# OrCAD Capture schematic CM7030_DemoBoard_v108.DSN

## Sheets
1 00.NOTE: title: CMA175; rev: 1.08; company: C-MEDIA ELECTRONICS Inc.; note: Note; note: 6F., 100, Sec. 4, Civil Boulevard, Taipei, Taiwan, R.O.C.
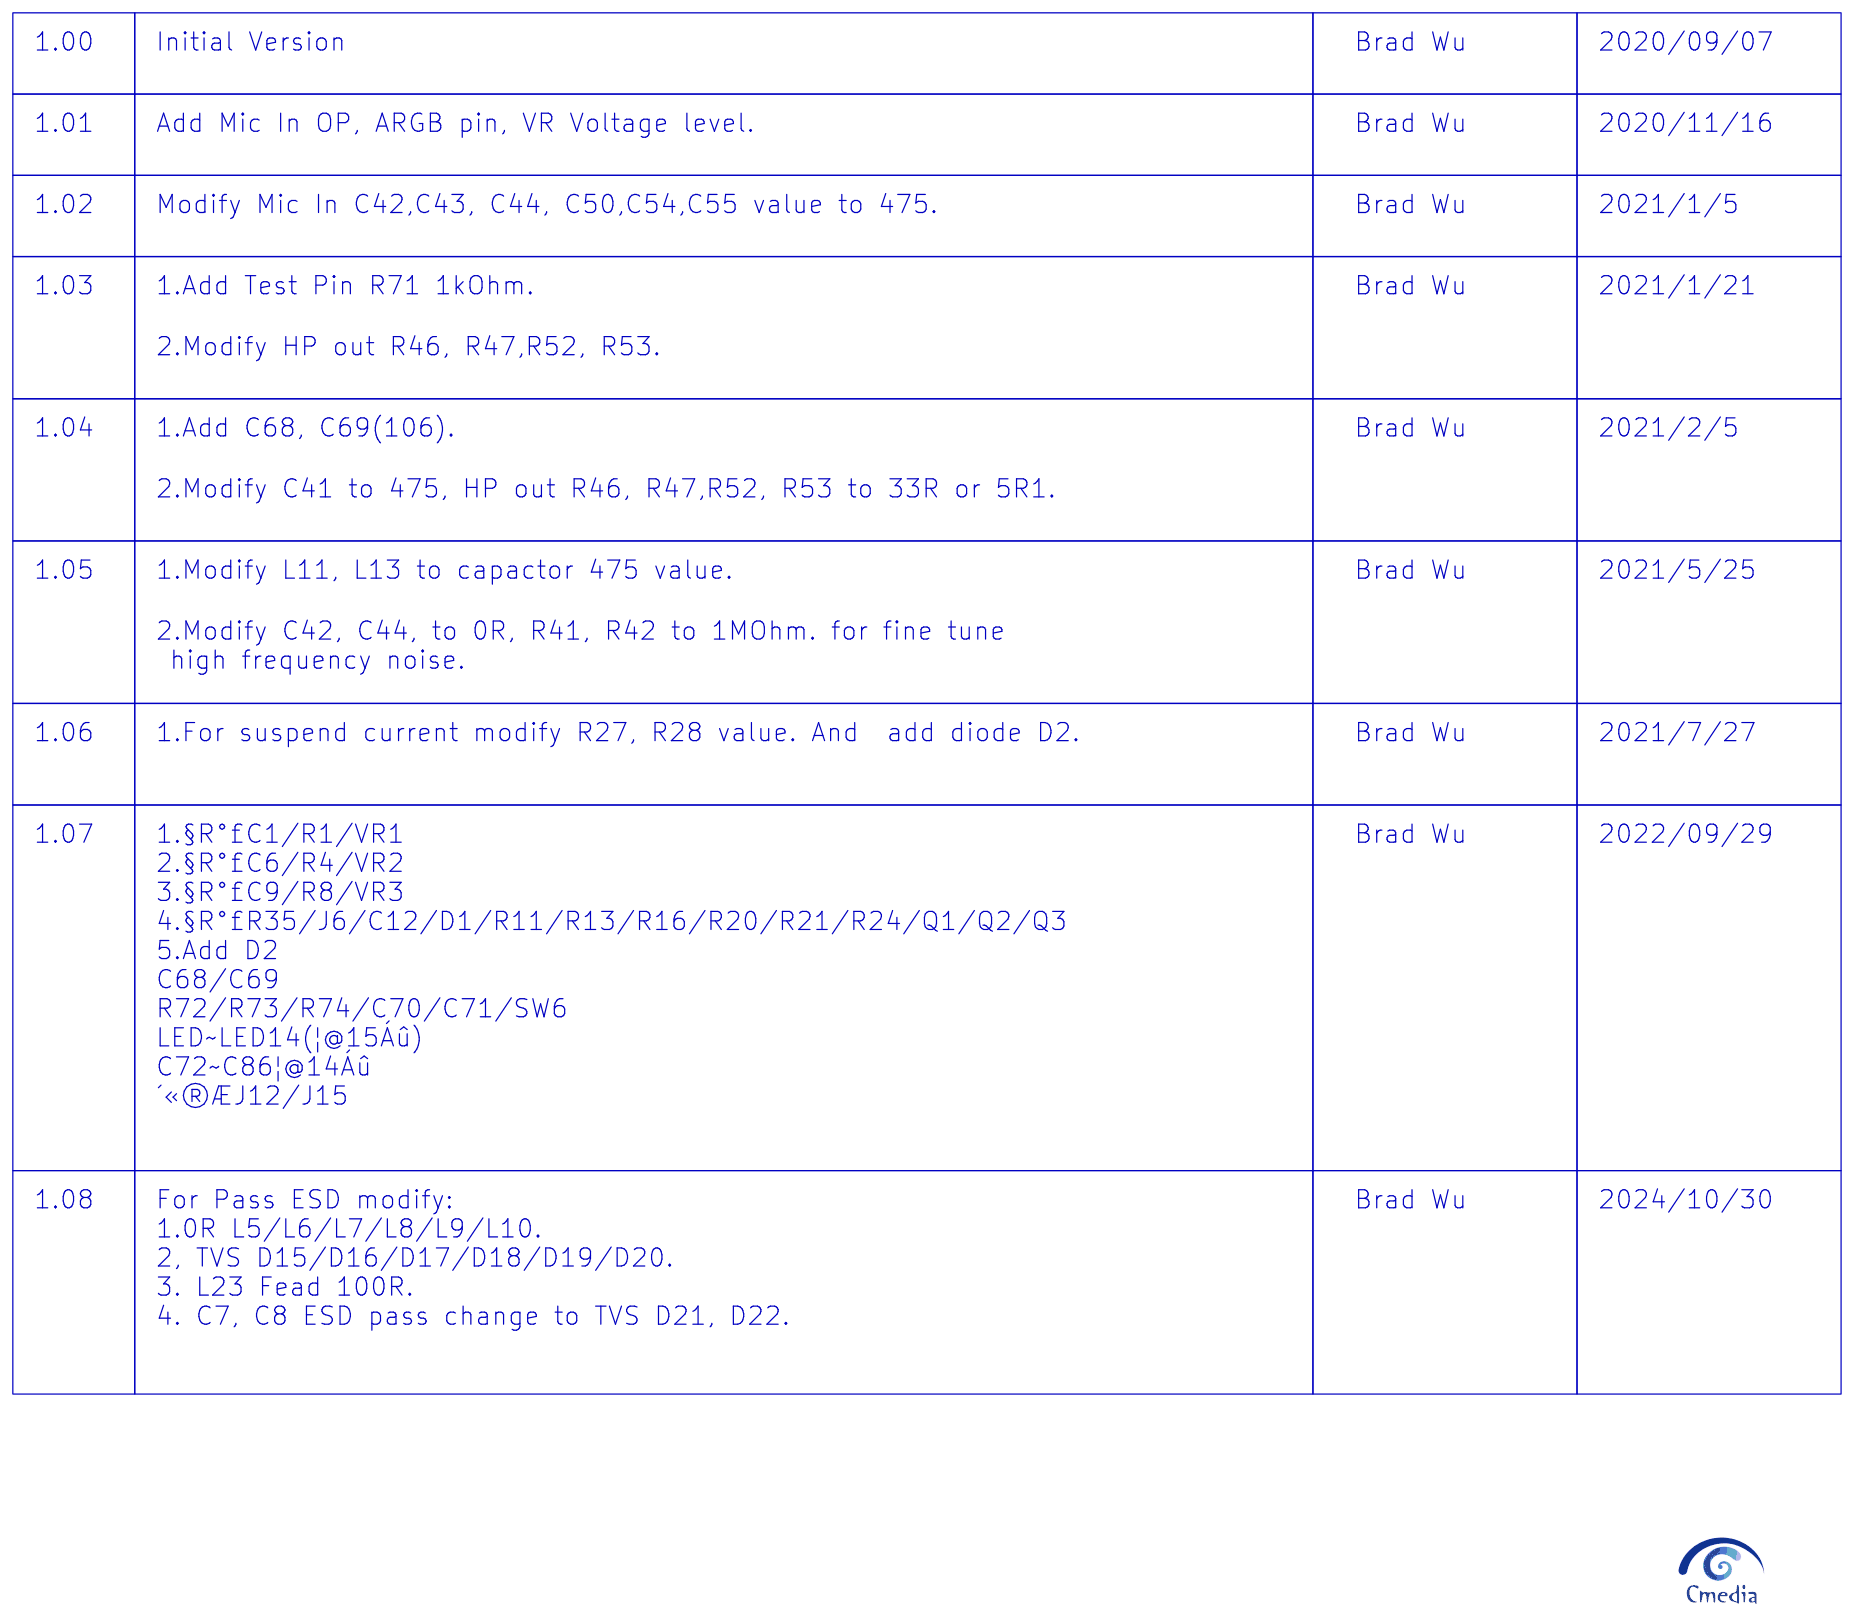
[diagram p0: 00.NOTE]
2 01.BLOCK: note: Block
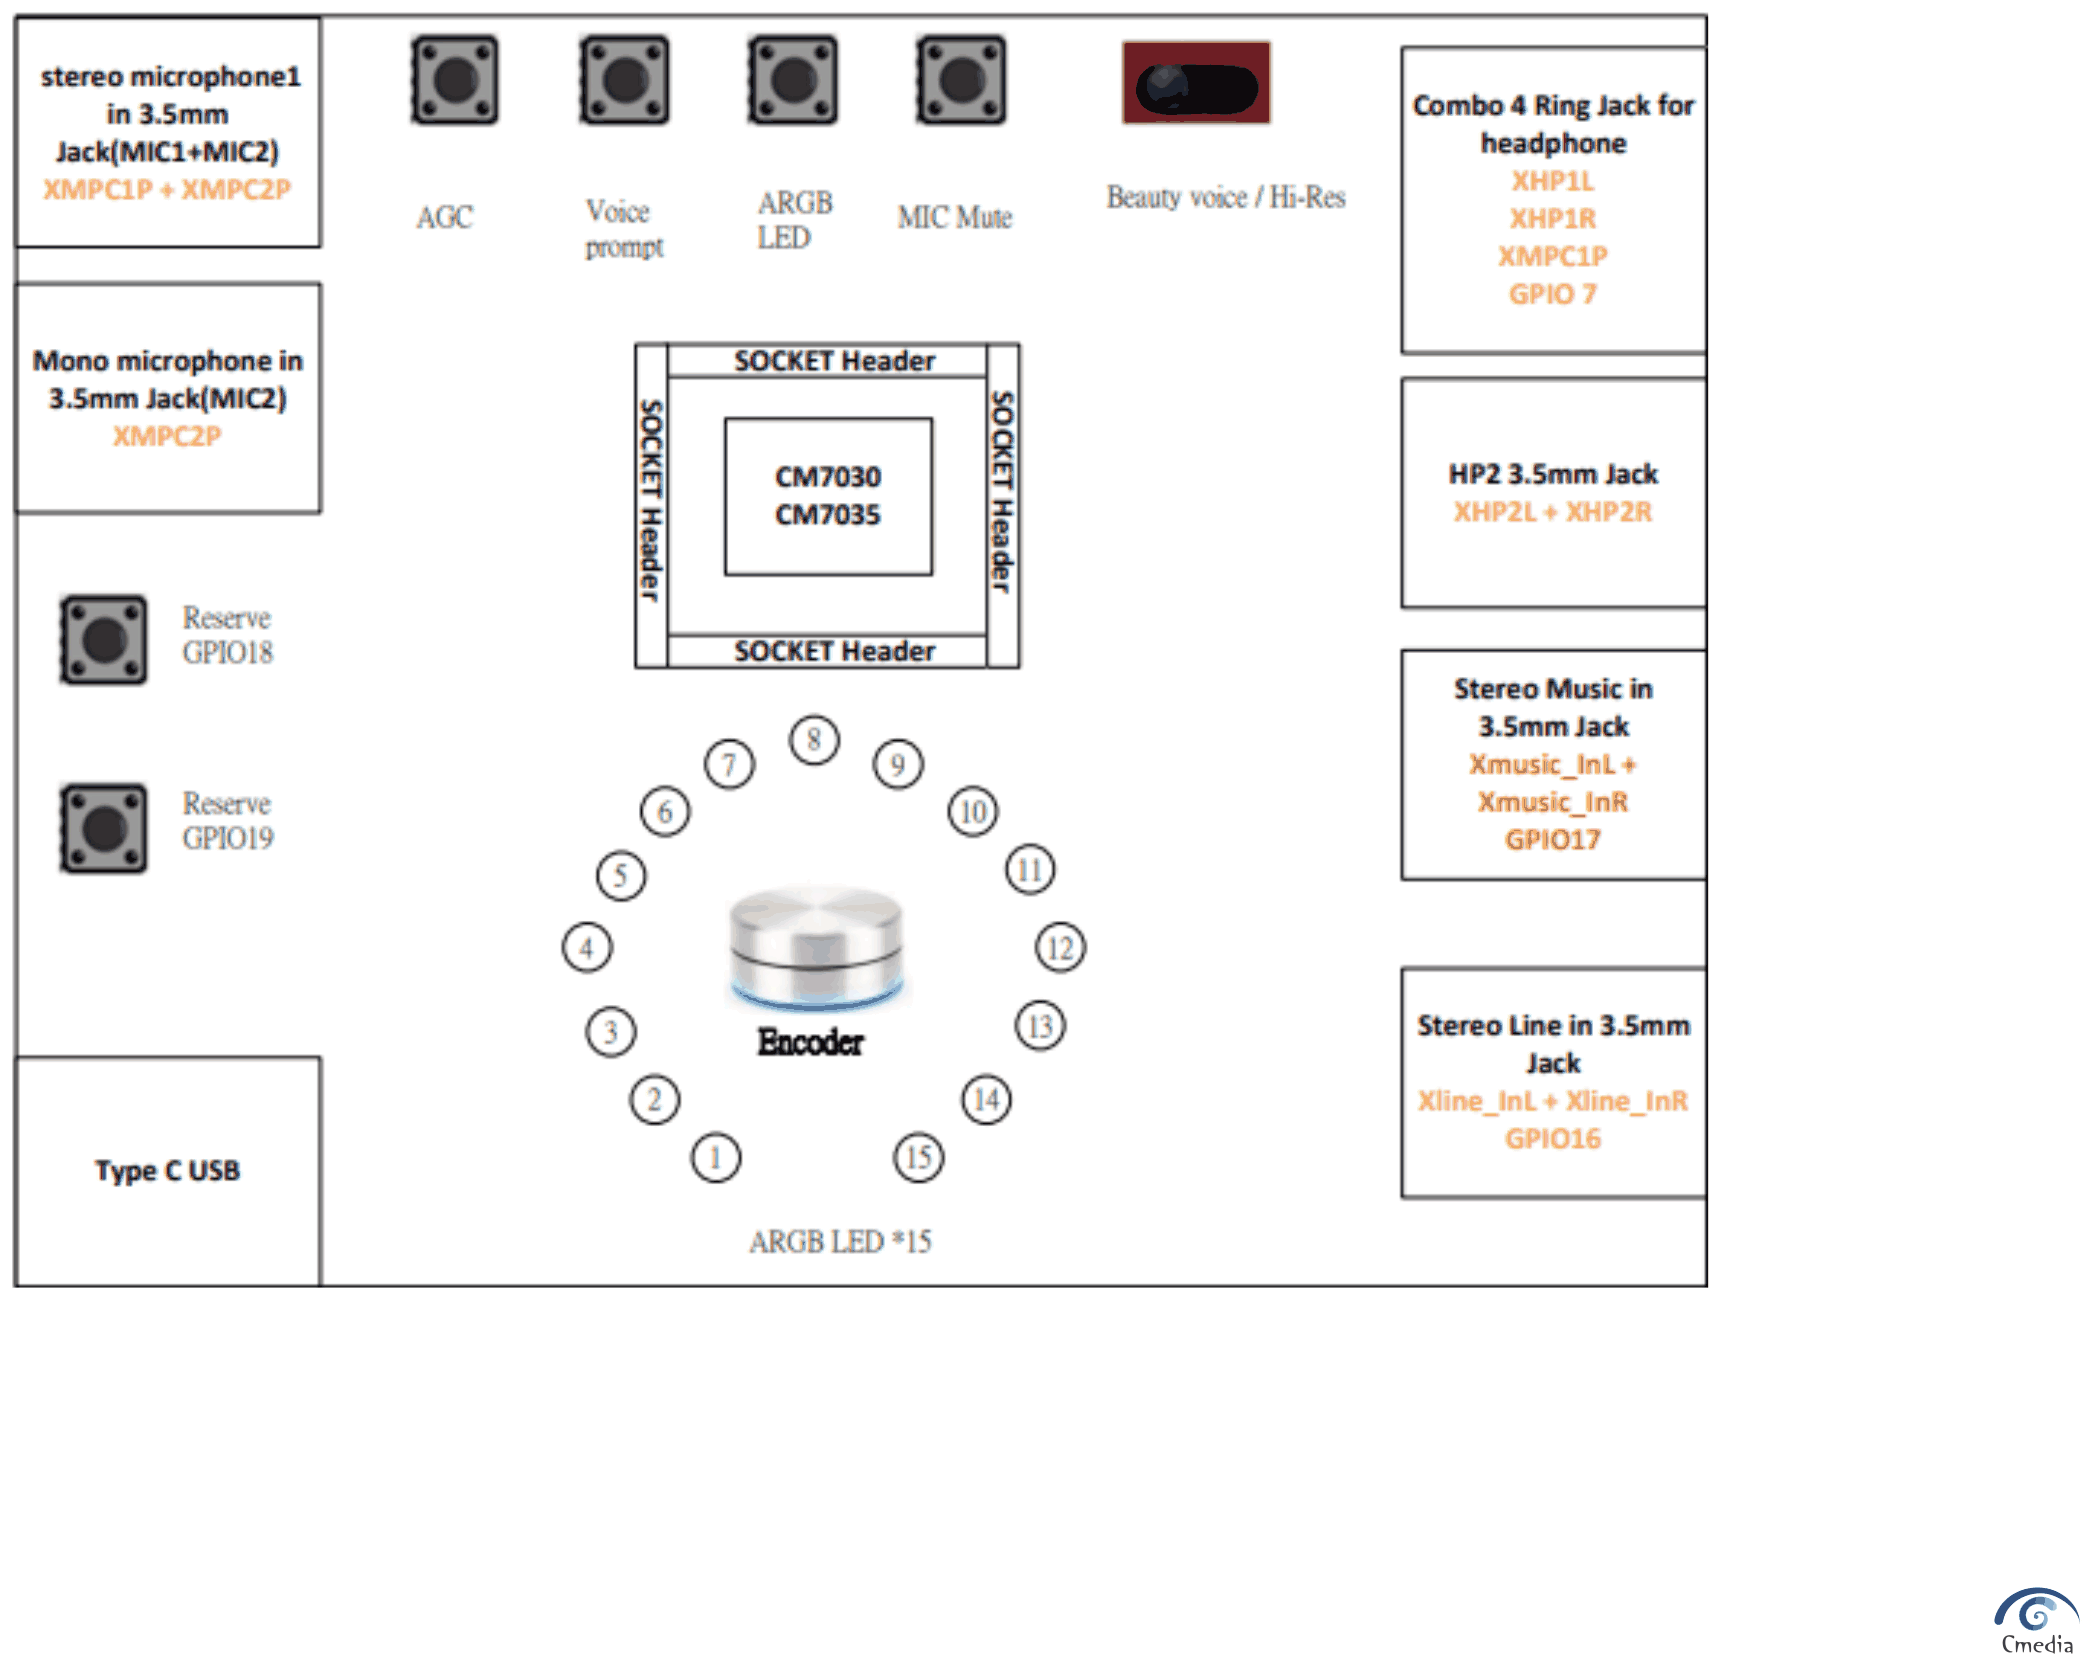
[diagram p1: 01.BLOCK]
3 02.PLACEMENT: note: Placement
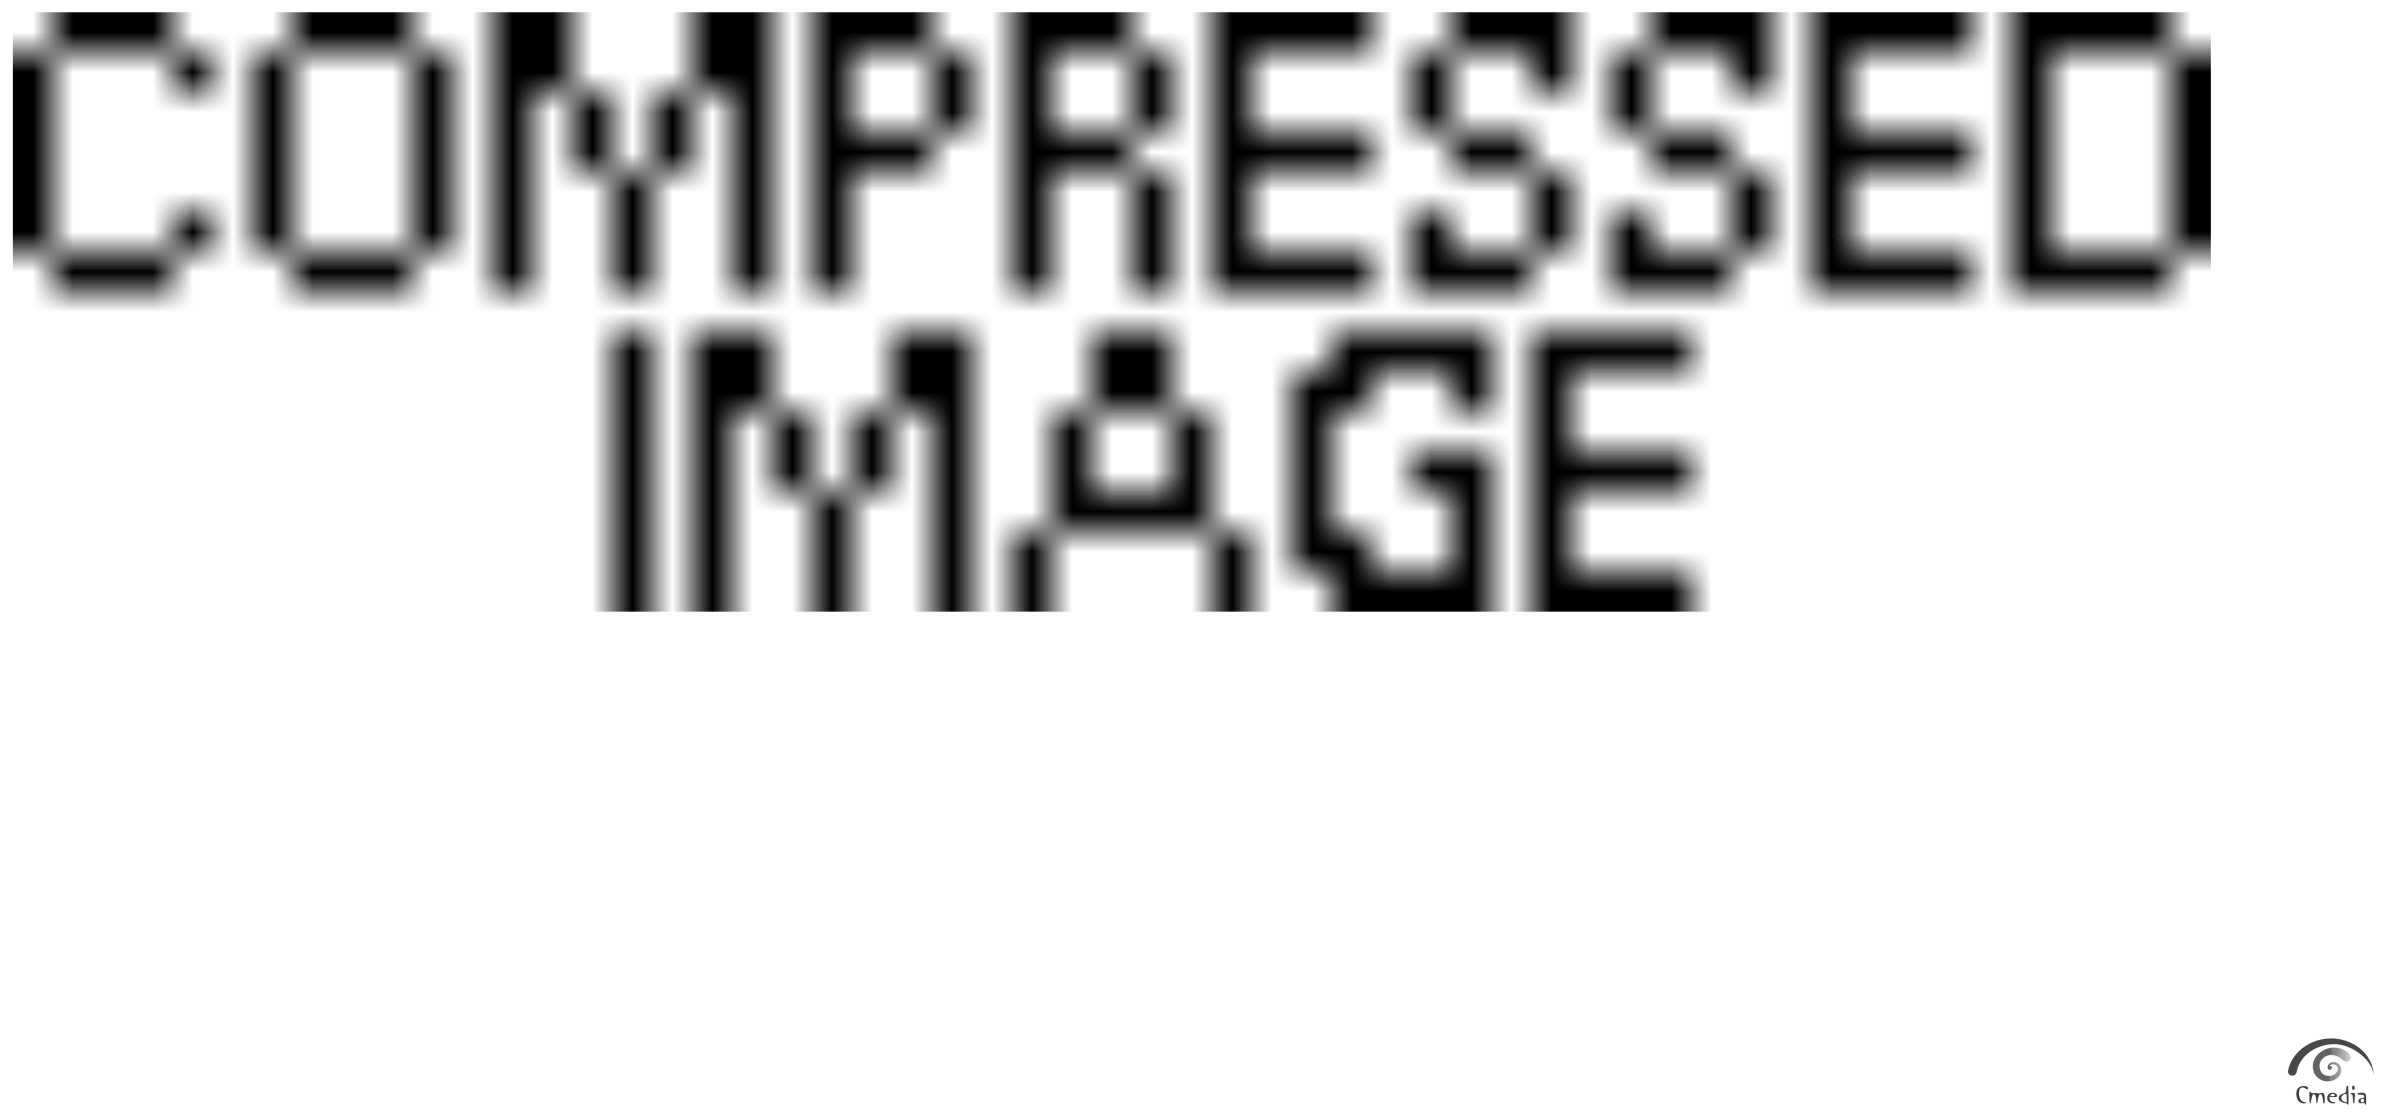
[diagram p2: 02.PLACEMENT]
4 03.CM7030: size B; note: CM7030
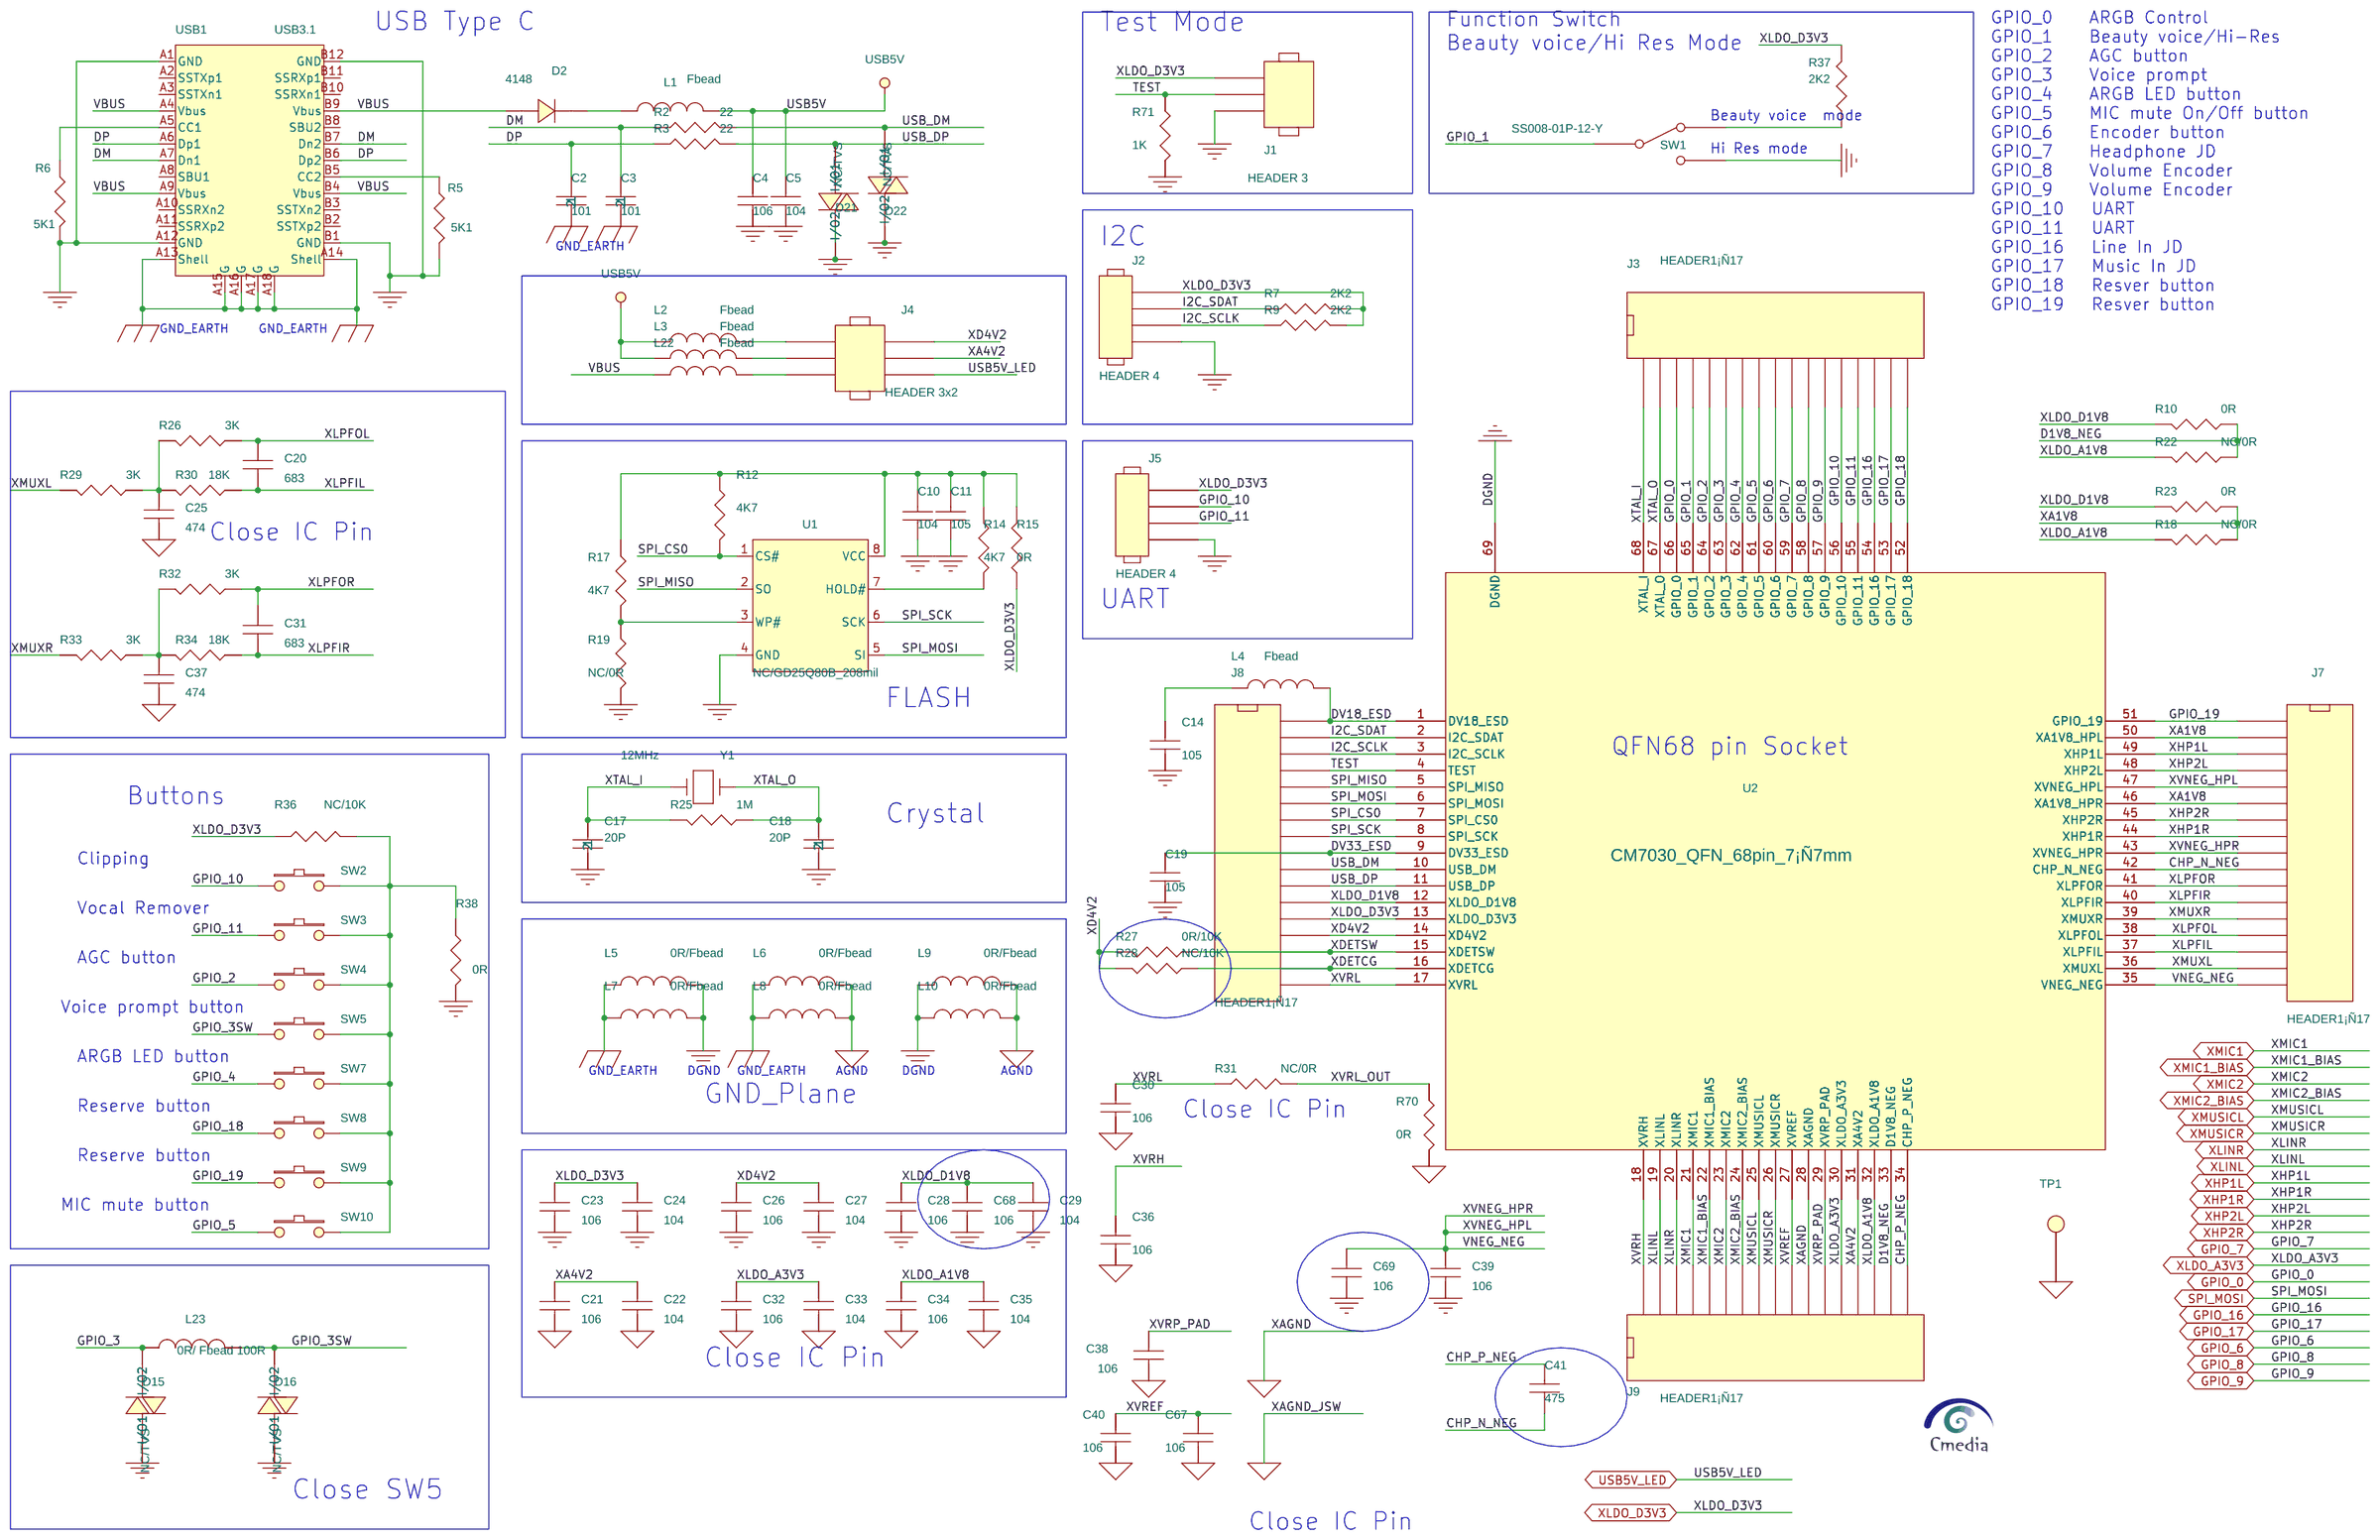
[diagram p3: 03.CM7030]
5 04.PHONE JACK: size Custom; note: PHONE JACK
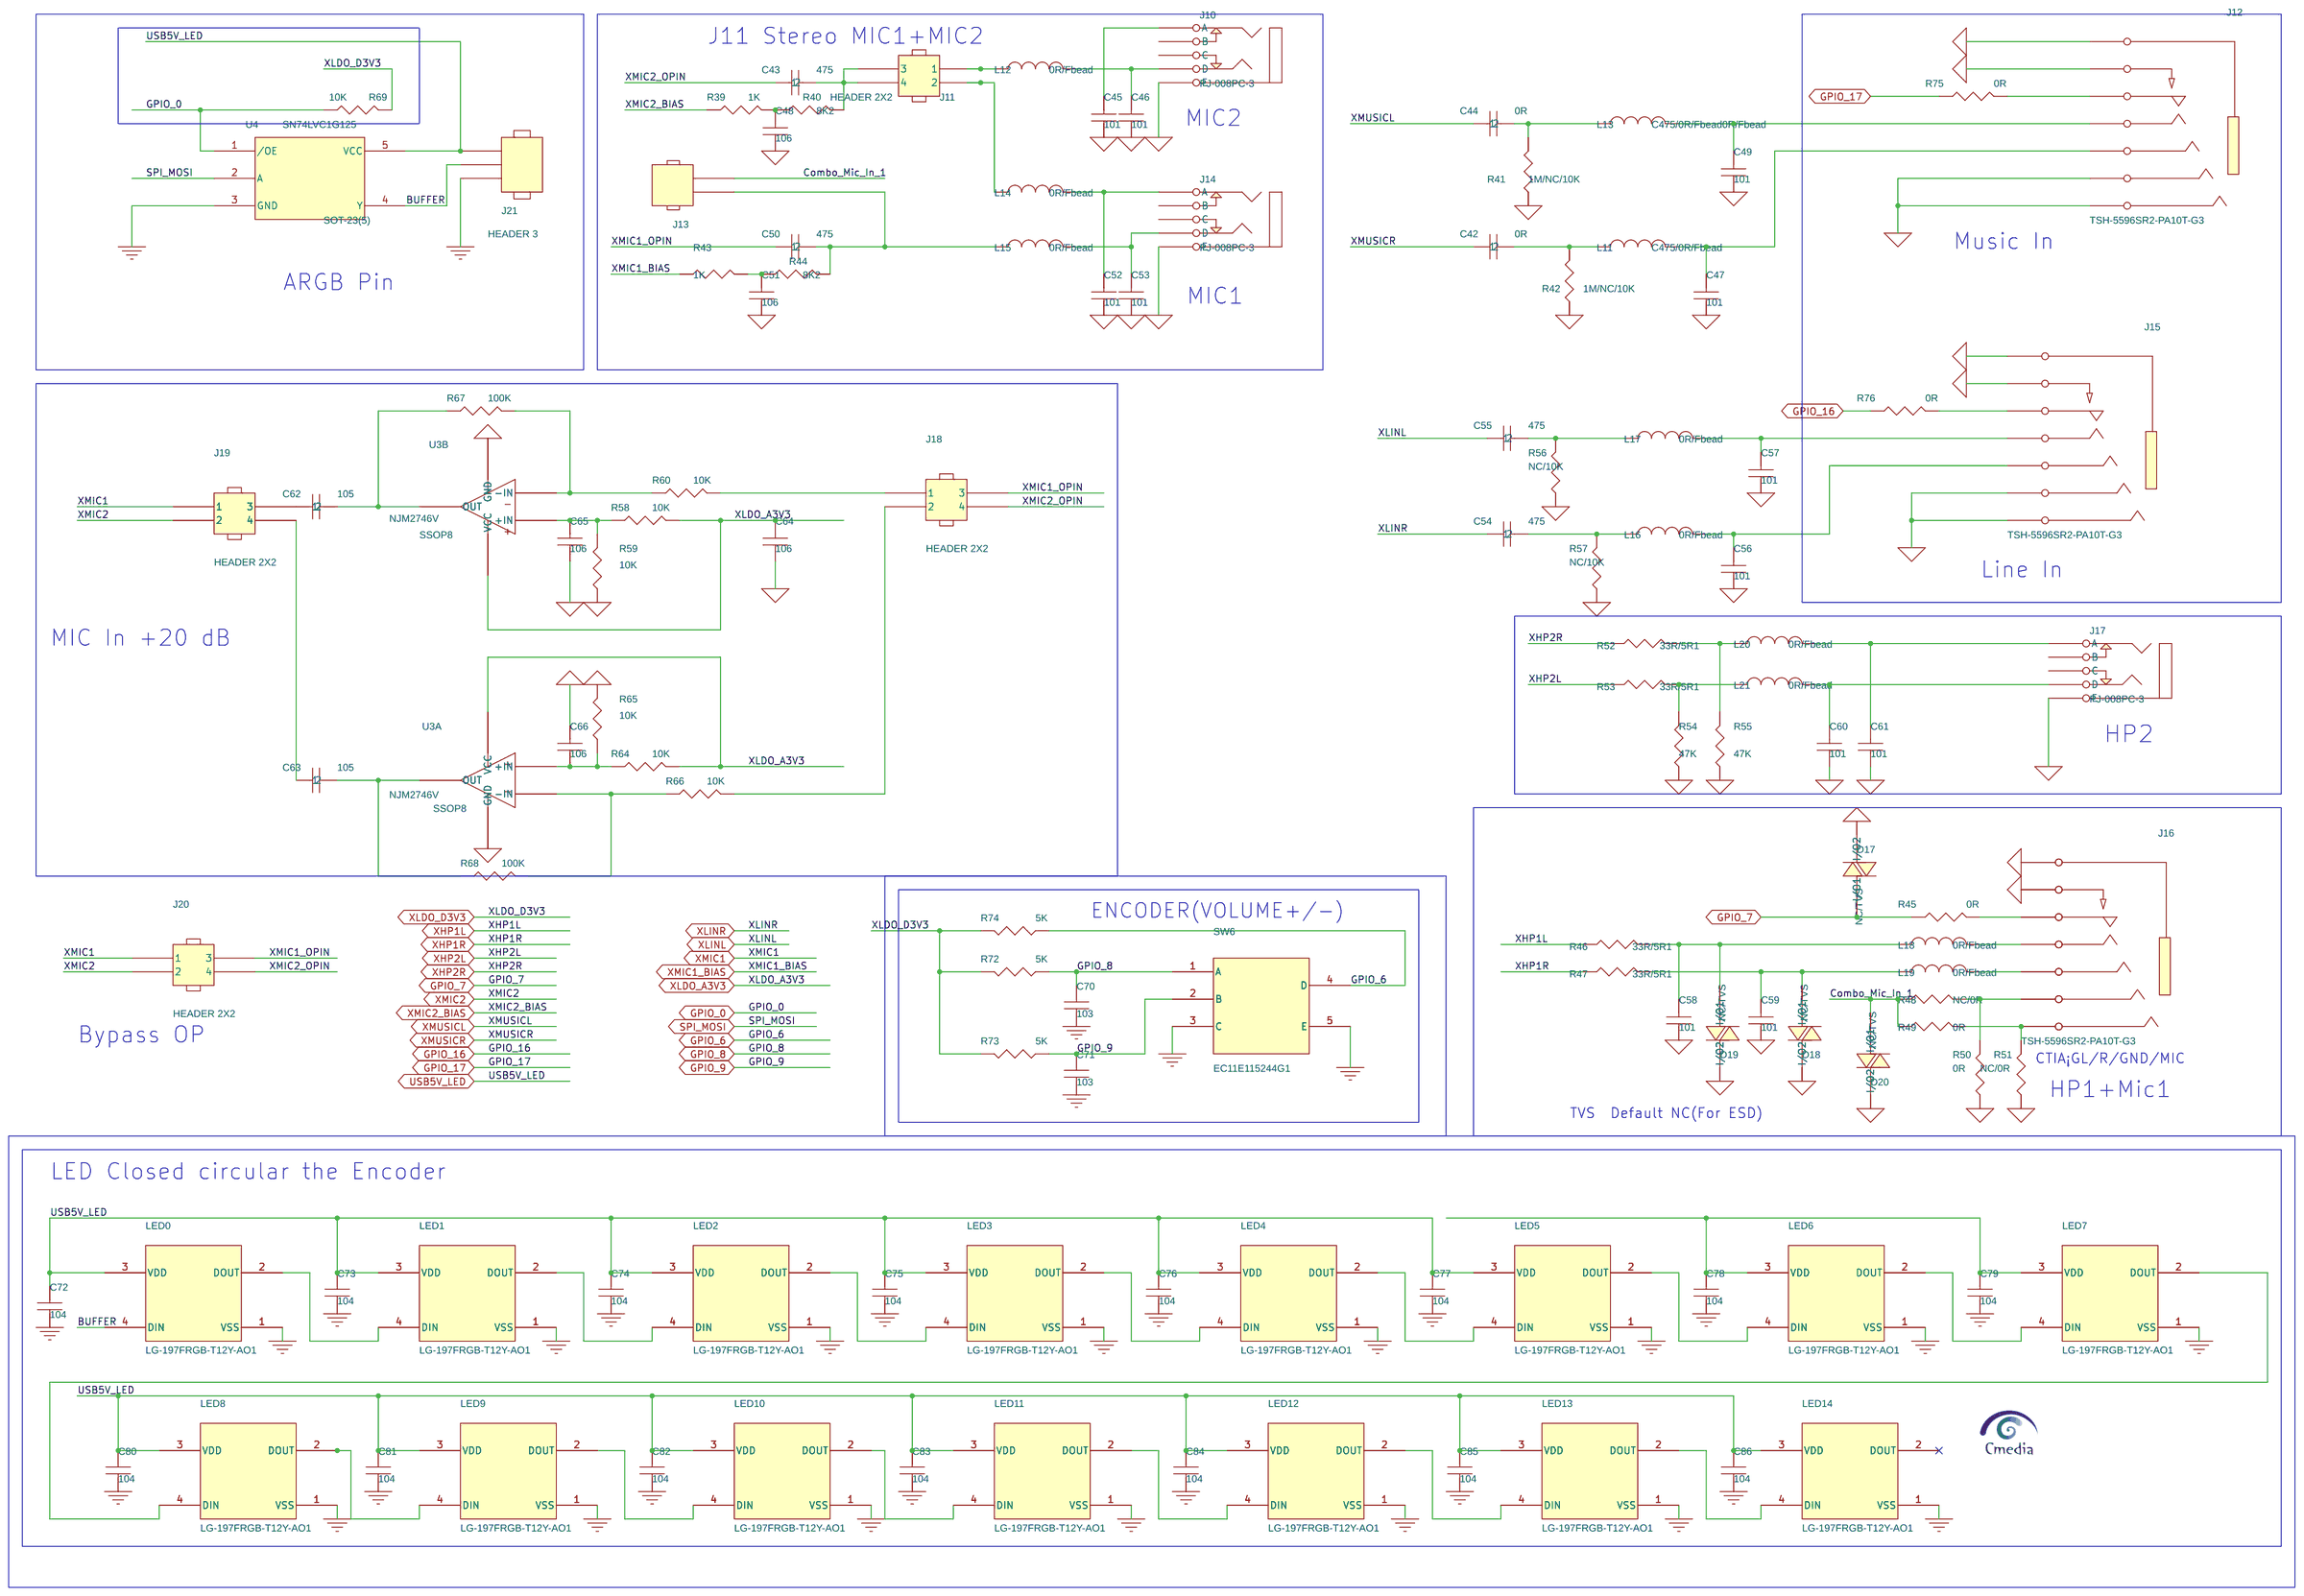
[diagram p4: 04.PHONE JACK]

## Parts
sheet 03.CM7030
C2  101  [SC0603]
C3  101  [SC0603]
C4  106  [SC0603]
C5  104  [SC0603]
C10  104  [SC0603]
C11  105  [SC0603]
C14  105  [SC0603]
C17  20P  [SC0603]
C18  20P  [SC0603]
C19  105  [SC0603]
C20  683  [SC0603]
C21  106  [SC0603]
C22  104  [SC0603]
C23  106  [SC0603]
C24  104  [SC0603]
C25  474  [SC0603]
C26  106  [SC0603]
C27  104  [SC0603]
C28  106  [SC0603]
C29  104  [SC0603]
C30  106  [SC0603]
C31  683  [SC0603]
C32  106  [SC0603]
C33  104  [SC0603]
C34  106  [SC0603]
C35  104  [SC0603]
C36  106  [SC0603]
C37  474  [SC0603]
C38  106  [SC0603]
C39  106  [SC0603]
C40  106  [SC0603]
C41  475  [SC0603]
C67  106  [SC0603]
C68  106  [SC0603]
C69  106  [SC0603]
D2  4148  [D1206]
D15  NC/TVS  [SOD-523]
D16  NC/TVS  [SOD-523]
D21  NC/TVS  [SOD-523]
D22  NC/TVS  [SOD-523]
J1  HEADER 3  [J1A3]
J2  HEADER 4  [J1A4]
J3  HEADER1¡Ñ17  [J2A22A]
J4  HEADER 3x2  [J2A6A]
J5  HEADER 4  [J1A4]
J7  HEADER1¡Ñ17  [J2A22A]
J8  HEADER1¡Ñ17  [J2A22A]
J9  HEADER1¡Ñ17  [J2A22A]
L1  Fbead  [SL0603]
L2  Fbead  [SL0603]
L3  Fbead  [SL0603]
L4  Fbead  [SL0603]
L5  0R/Fbead  [SL0603]
L6  0R/Fbead  [SL0603]
L7  0R/Fbead  [SL0603]
L8  0R/Fbead  [SL0603]
L9  0R/Fbead  [SL0603]
L10  0R/Fbead  [SL0603]
L22  Fbead  [SL0603]
L23  0R/ Fbead 100R  [SL0603]
R2  22  [SR0603]
R3  22  [SR0603]
R5  5K1  [SR0603]
R6  5K1  [SR0603]
R7  2K2  [SR0603]
R9  2K2  [SR0603]
R10  0R  [SR0603]
R12  4K7  [SR0603]
R14  4K7  [SR0603]
R15  0R  [SR0603]
R17  4K7  [SR0603]
R18  NC/0R  [SR0603]
R19  NC/0R  [SR0603]
R22  NC/0R  [SR0603]
R23  0R  [SR0603]
R25  1M  [SR0603]
R26  3K  [SR0603]
R27  0R/10K  [SR0603]
R28  NC/10K  [SR0603]
R29  3K  [SR0603]
R30  18K  [SR0603]
R31  NC/0R  [SR0603]
R32  3K  [SR0603]
R33  3K  [SR0603]
R34  18K  [SR0603]
R36  NC/10K  [SR0603]
R37  2K2  [SR0603]
R38  0R  [SR0603]
R70  0R  [SR0603]
R71  1K  [SR0603]
SW1  SS008-01P-12-Y  [SLSW-3P]
SW2  CTT-1135  [STSW-1135]
SW3  CTT-1135  [STSW-1135]
SW4  CTT-1135  [STSW-1135]
SW5  CTT-1135  [STSW-1135]
SW7  CTT-1135  [STSW-1135]
SW8  CTT-1135  [STSW-1135]
SW9  CTT-1135  [STSW-1135]
SW10  CTT-1135  [STSW-1135]
TP1  TP1  [TP60]
U1  NC/GD25Q80B_208mil  [SU008ADA-208]
U2  CM7030_QFN_68pin_7¡Ñ7mm  [SU068QFN-SKTP0.4]
USB1  USB3.1  [SUSB3.1CTYPE-RS13KN-CM]
Y1  12MHz  [BXS]
sheet 04.PHONE JACK
C42  0R  [SC0603]
C43  475  [SC0603]
C44  0R  [SC0603]
C45  101  [SC0603]
C46  101  [SC0603]
C47  101  [SC0603]
C48  106  [SC0603]
C49  101  [SC0603]
C50  475  [SC0603]
C51  106  [SC0603]
C52  101  [SC0603]
C53  101  [SC0603]
C54  475  [SC0603]
C55  475  [SC0603]
C56  101  [SC0603]
C57  101  [SC0603]
C58  101  [SC0603]
C59  101  [SC0603]
C60  101  [SC0603]
C61  101  [SC0603]
C62  105  [SC0603]
C63  105  [SC0603]
C64  106  [SC0603]
C65  106  [SC0603]
C66  106  [SC0603]
C70  103  [C0603]
C71  103  [C0603]
C72  104  [C0603]
C73  104  [C0603]
C74  104  [C0603]
C75  104  [C0603]
C76  104  [C0603]
C77  104  [C0603]
C78  104  [C0603]
C79  104  [C0603]
C80  104  [C0603]
C81  104  [C0603]
C82  104  [C0603]
C83  104  [C0603]
C84  104  [C0603]
C85  104  [C0603]
C86  104  [C0603]
D17  NC/TVS  [SOD-523]
D18  NC/TVS  [SOD-523]
D19  NC/TVS  [SOD-523]
D20  NC/TVS  [SOD-523]
J10  PJ-008PC-3  [PHONEJACK9]
J11  HEADER 2X2  [J2A4A]
J12  TSH-5596SR2-PA10T-G3  [PHONEJACK-5596SR2]
J13  HEADER 2  [J1A2]
J14  PJ-008PC-3  [PHONEJACK9]
J15  TSH-5596SR2-PA10T-G3  [PHONEJACK-5596SR2]
J16  TSH-5596SR2-PA10T-G3  [PHONEJACK-5596SR2]
J17  PJ-008PC-3  [PHONEJACK9]
J18  HEADER 2X2
J19  HEADER 2X2
J20  HEADER 2X2
J21  HEADER 3  [J1A3]
L11  C475/0R/Fbead  [SL0603]
L12  0R/Fbead  [SL0603]
L13  C475/0R/Fbead0R/Fbead  [SL0603]
L14  0R/Fbead  [SL0603]
L15  0R/Fbead  [SL0603]
L16  0R/Fbead  [SL0603]
L17  0R/Fbead  [SL0603]
L18  0R/Fbead  [SL0603]
L19  0R/Fbead  [SL0603]
L20  0R/Fbead  [SL0603]
L21  0R/Fbead  [SL0603]
LED0  LG-197FRGB-T12Y-AO1
LED1  LG-197FRGB-T12Y-AO1
LED2  LG-197FRGB-T12Y-AO1
LED3  LG-197FRGB-T12Y-AO1
LED4  LG-197FRGB-T12Y-AO1
LED5  LG-197FRGB-T12Y-AO1
LED6  LG-197FRGB-T12Y-AO1
LED7  LG-197FRGB-T12Y-AO1
LED8  LG-197FRGB-T12Y-AO1
LED9  LG-197FRGB-T12Y-AO1
LED10  LG-197FRGB-T12Y-AO1
LED11  LG-197FRGB-T12Y-AO1
LED12  LG-197FRGB-T12Y-AO1
LED13  LG-197FRGB-T12Y-AO1
LED14  LG-197FRGB-T12Y-AO1
R39  1K  [SR0603]
R40  8K2  [SR0603]
R41  1M/NC/10K  [SR0603]
R42  1M/NC/10K  [SR0603]
R43  1K  [SR0603]
R44  8K2  [SR0603]
R45  0R  [SR0603]
R46  33R/5R1  [SR0603]
R47  33R/5R1  [SR0603]
R48  NC/0R  [SR0603]
R49  0R  [SR0603]
R50  0R  [SR0603]
R51  NC/0R  [SR0603]
R52  33R/5R1  [SR0603]
R53  33R/5R1  [SR0603]
R54  47K  [SR0603]
R55  47K  [SR0603]
R56  NC/10K  [SR0603]
R57  NC/10K  [SR0603]
R58  10K  [SR0603]
R59  10K  [SR0603]
R60  10K  [SR0603]
R64  10K  [SR0603]
R65  10K  [SR0603]
R66  10K  [SR0603]
R67  100K  [SR0603]
R68  100K  [SR0603]
R69  10K  [SR0603]
R72  5K
R73  5K
R74  5K
R75  0R  [SR0603]
R76  0R  [SR0603]
SW6  EC11E115244G1
U3  NJM2746V  [SSOP8]  (sections A,B)
U4  SN74LVC1G125  [SOT-23(5)]

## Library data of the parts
C2 C55 = C_2
C3 C43 = C_3
C4 C5 C14 C19-C41 C67-C69 = CAPACITOR_NON-POL
C10 C85 = CAP_NP_1
C11 C82 = CAP_NP
C17 C54 = C_1
C18 C44 = C
D2 = DIODE
D15-D22 = DA108S1_SO_2
J1 J21 = HEADER_3
J2 J5 = HEADER_5_3
J3 J7-J9 = CONN_SOCKET_40_6
J4 = HEADER_3x2_SM
L1-L23 = INDUCTOR
R2 R3 R5-R7 R9 R10 R12 R14 R15 R17-R19 R22 R23 R25-R34 R36-R60 R64-R76 = R
SW1 = SW_SPDT
SW2-SW5 SW7-SW10 = SW_PUSHBUTTON
TP1 = TEST_POINT_1
U1 = EPC1_LCC_0
U2 = CMI120_21
USB1 = HEADER_4_1: 1ST PART FIELD: USB Micro B-Type SMD
Y1 = ZTA
C42 = C_7
C45 = CAP_NP_8
C46 = CAP_NP_19
C47 = CAP_NP_20
C48 = CAP_NP_2
C49 = CAP_NP_22
C50 = C_4
C51 = CAP_NP_13
C52 = CAP_NP_4
C53 = CAP_NP_14
C56 = CAP_NP_5
C57 = CAP_NP_17
C58 = CAP_NP_6
C59 = CAP_NP_28
C60 = CAP_NP_12
C61 = CAP_NP_16
C62 = C_5
C63 = C_6
C64 = CAP_NP_11
C65 = CAP_NP_25
C66 = CAP_NP_32
C70 = CAP_NP_7
C71 = CAP_NP_21
C72 = CAP_NP_23
C73 = CAP_NP_30
C74 = CAP_NP_31
C75 = CAP_NP_27
C76 = CAP_NP_29
C77 = CAP_NP_33
C78 = CAP_NP_3
C79 = CAP_NP_9
C80 = CAP_NP_18
C81 = CAP_NP_26
C83 = CAP_NP_10
C84 = CAP_NP_24
C86 = CAP_NP_15
J10 J14 J17 = PHONEJACK_STEREO_SW_0: 1ST PART FIELD: Line OUT
J11 J18-J20 = HEADER_2X2
J12 J15 J16 = PHONEJACK_STEREO_SW_15
J13 = HEADER_2
LED0-LED14 = X72011_4
SW6 = X72011_5
U3 = OP-14
U4 = LM78L05AC_TO92_0

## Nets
AGND: C21.2 C22.2 C25.2 C30.2 C32.2 C33.2 C34.2 C35.2 C36.2 C37.2 C38.2 C40.2 C45.1 C46.1 C47.1 C48.1 C49.1 C51.1 C52.1 C53.1 C56.1 C57.1 C58.1 C59.1 C60.1 C61.1 C64.1 C65.1 C66.2 C67.2 D17.2(I/O2) D18.2(I/O2) D19.2(I/O2) D20.2(I/O2) J9.11 J10.1(E) J12.3 J12.4 J12.6 J12.7 J14.1(E) J15.3 J15.4 J15.6 J15.7 J16.6 J16.7 J17.1(E) L6.2 L8.2 L9.2 L10.2 R41.1 R42.1 R50.1 R51.1 R54.1 R55.1 R56.1 R57.1 R59.2 R65.1 R70.2 TP1.1 U2.28(XAGND) U3.4(GND)
D1V8_NEG: J9.16 R10.1 R22.1 U2.33(D1V8_NEG)
DGND: C4.2 C5.2 C10.1 C11.1 C14.2 C17.2 C18.2 C19.2 C23.2 C24.2 C26.2 C27.2 C28.2 C29.2 C39.2 C68.2 C69.2 C70.2 C71.2 C72.2 C73.2 C74.2 C75.2 C76.2 C77.2 C78.2 C79.2 C80.2 C81.2 C82.2 C83.2 C84.2 C85.2 C86.2 D15.1(I/O1) D16.1(I/O1) D21.2(I/O2) D22.2(I/O2) J1.3 J2.4 J5.4 J21.3 L5.2 L7.2 L9.1 L10.1 LED0.1(VSS) LED1.1(VSS) LED2.1(VSS) LED3.1(VSS) LED4.1(VSS) LED5.1(VSS) LED6.1(VSS) LED7.1(VSS) LED8.1(VSS) LED9.1(VSS) LED10.1(VSS) LED11.1(VSS) LED12.1(VSS) LED13.1(VSS) LED14.1(VSS) R5.2 R6.2 R19.2 R38.2 R71.2 SW1.3(NO) SW6.3(C) SW6.5(E) U1.4(GND) U2.69(DGND) U4.3(GND) USB1.A1(GND) USB1.A12(GND) USB1.B1(GND) USB1.B12(GND)
DV18_ESD: J8.1 L4.2 U2.1(DV18_ESD)
DV33_ESD: C19.1 J8.9 U2.9(DV33_ESD)
GND_EARTH: C2.2 C3.2 L5.1 L6.1 L7.1 L8.1 USB1.A13(Shell) USB1.A14(Shell) USB1.A15(G) USB1.A16(G) USB1.A17(G) USB1.A18(G)
VBUS: D2.1(A) L22.1 USB1.A4(Vbus) USB1.A9(Vbus) USB1.B4(Vbus) USB1.B9(Vbus)
BUFFER: J21.2 LED0.4(DIN) U4.4(Y)
CHP_N_NEG: C41.2 J7.10 U2.42(CHP_N_NEG)
CHP_P_NEG: C41.1 J9.17 U2.34(CHP_P_NEG)
Combo_Mic_In_1: D20.1(I/O1) J13.1 R48.1 R49.1
DM: C3.1 R2.2 USB1.A7(Dn1) USB1.B7(Dn2)
DP: C2.1 R3.2 USB1.A6(Dp1) USB1.B6(Dp2)
GPIO_0: J3.3 R69.1 U2.66(GPIO_0) U4.1(/OE)
GPIO_1: J3.4 SW1.2(COMMON) U2.65(GPIO_1)
GPIO_2: J3.5 SW4.1 U2.64(GPIO_2)
GPIO_3: D15.2(I/O2) J3.6 L23.1 U2.63(GPIO_3)
GPIO_3SW: D16.2(I/O2) L23.2 SW5.1
GPIO_4: J3.7 SW7.1 U2.62(GPIO_4)
GPIO_5: J3.8 SW10.1 U2.61(GPIO_5)
GPIO_6: J3.9 R74.2 SW6.4(D) U2.60(GPIO_6)
GPIO_7: D17.1(I/O1) J3.10 R45.1 U2.59(GPIO_7)
GPIO_8: C70.1 J3.11 R72.2 SW6.1(A) U2.58(GPIO_8)
GPIO_9: C71.1 J3.12 R73.2 SW6.2(B) U2.57(GPIO_9)
GPIO_10: J3.13 J5.2 SW2.1 U2.56(GPIO_10)
GPIO_11: J3.14 J5.3 SW3.1 U2.55(GPIO_11)
GPIO_16: J3.15 R76.1 U2.54(GPIO_16)
GPIO_17: J3.16 R75.1 U2.53(GPIO_17)
GPIO_18: J3.17 SW8.1 U2.52(GPIO_18)
GPIO_19: J7.1 SW9.1 U2.51(GPIO_19)
I2C_SCLK: J2.3 J8.3 R9.1 U2.3(I2C_SCLK)
I2C_SDAT: J2.2 J8.2 R7.1 U2.2(I2C_SDAT)
SPI_CS0: J8.7 R12.2 U1.1(CS#) U2.7(SPI_CS0)
SPI_MISO: J8.5 U1.2(SO) U2.5(SPI_MISO)
SPI_MOSI: J8.6 U1.5(SI) U2.6(SPI_MOSI) U4.2(A)
SPI_SCK: J8.8 U1.6(SCK) U2.8(SPI_SCK)
TEST: J1.2 J8.4 R71.1 U2.4(TEST)
USB5V: C4.1 C5.1 L1.2 L2.1 L3.1
USB5V_LED: C72.1 C73.1 C74.1 C75.1 C76.1 C77.1 C80.1 C81.1 C82.1 C83.1 C84.1 C85.1 C86.1 J4.6 J21.1 LED0.3(VDD) LED1.3(VDD) LED2.3(VDD) LED3.3(VDD) LED4.3(VDD) LED5.3(VDD) LED8.3(VDD) LED9.3(VDD) LED10.3(VDD) LED11.3(VDD) LED12.3(VDD) LED13.3(VDD) LED14.3(VDD) U4.5(VCC)
USB_DM: D22.1(I/O1) J8.10 R2.1 U2.10(USB_DM)
USB_DP: D21.1(I/O1) J8.11 R3.1 U2.11(USB_DP)
VNEG_NEG: C39.1 C69.1 J7.5 J7.9 J7.17 U2.35(VNEG_NEG) U2.43(XVNEG_HPR) U2.47(XVNEG_HPL)
XA1V8: J7.2 J7.6 R18.1 R23.1 U2.46(XA1V8_HPR) U2.50(XA1V8_HPL)
XA4V2: C21.1 C22.1 J4.4 J9.14 U2.31(XA4V2)
XD4V2: C26.1 C27.1 J4.2 J8.14 R27.2 R28.2 U2.14(XD4V2)
XDETCG: J8.16 R28.1 U2.16(XDETCG)
XDETSW: J8.15 R27.1 U2.15(XDETSW)
XHP1L: J7.3 R46.1 U2.49(XHP1L)
XHP1R: J7.8 R47.1 U2.44(XHP1R)
XHP2L: J7.4 R53.1 U2.48(XHP2L)
XHP2R: J7.7 R52.1 U2.45(XHP2R)
XLDO_A1V8: C34.1 C35.1 J9.15 R18.2 R22.2 U2.32(XLDO_A1V8)
XLDO_A3V3: C32.1 C33.1 C64.2 J9.13 R58.1 R64.1 U2.30(XLDO_A3V3) U3.8(VCC)
XLDO_D1V8: C28.1 C29.1 C68.1 J8.12 R10.2 R23.2 U2.12(XLDO_D1V8)
XLDO_D3V3: C23.1 C24.1 J1.1 J2.1 J5.1 J8.13 R7.2 R9.2 R15.1 R36.1 R37.1 R69.2 R72.1 R73.1 R74.1 U2.13(XLDO_D3V3)
XLINL: C55.1 J9.2 U2.19(XLINL)
XLINR: C54.1 J9.3 U2.20(XLINR)
XLPFIL: C20.2 J7.15 R30.1 U2.37(XLPFIL)
XLPFIR: C31.2 J7.12 R34.1 U2.40(XLPFIR)
XLPFOL: C20.1 J7.14 R26.1 U2.38(XLPFOL)
XLPFOR: C31.1 J7.11 R32.1 U2.41(XLPFOR)
XMIC1: J9.4 J19.3(1) J20.3(1) U2.21(XMIC1)
XMIC1_BIAS: J9.5 R43.2 U2.22(XMIC1_BIAS)
XMIC1_OPIN: C50.1 J18.1(3) J20.1(3)
XMIC2: J9.6 J19.4(2) J20.4(2) U2.23(XMIC2)
XMIC2_BIAS: J9.7 R39.2 U2.24(XMIC2_BIAS)
XMIC2_OPIN: C43.1 J18.2(4) J20.2(4)
XMUSICL: C44.1 J9.8 U2.25(XMUSICL)
XMUSICR: C42.1 J9.9 U2.26(XMUSICR)
XMUXL: J7.16 R29.2 U2.36(XMUXL)
XMUXR: J7.13 R33.2 U2.39(XMUXR)
XTAL_I: C17.1 J3.1 R25.2 U2.68(XTAL_I) Y1.2
XTAL_O: C18.1 J3.2 R25.1 U2.67(XTAL_O) Y1.1
XVREF: C40.1 C67.1 J9.10 U2.27(XVREF)
XVRH: C36.1 J9.1 U2.18(XVRH)
XVRL: C30.1 J8.17 R31.1 U2.17(XVRL)
XVRL_OUT: R31.2 R70.1
XVRP_PAD: C38.1 J9.12 U2.29(XVRP_PAD)
N14895: C46.2 J10.5(D) L12.2
N14917: C45.2 J10.2(A)
N16497134: C25.1 R26.2 R29.1 R30.2
N16504658: C37.1 R32.2 R33.1 R34.2
N16605417: R36.2 R38.1 SW2.2 SW3.2 SW4.2 SW5.2 SW7.2 SW8.2 SW9.2 SW10.2
N16939385: C52.2 J14.2(A) L14.2
N16939395: C53.2 J14.5(D) L15.2
N16939474: C43.2 J11.1(3) J11.2(4) R40.2
N16939566: C51.2 R43.1 R44.1
N16939605: C50.2 J13.2 L15.1 R44.2
N16974601: C57.2 J15.1 L17.2
N16974734: C56.2 J15.2 L16.2
N18658830: C58.2 D19.1(I/O1) L18.1 R46.2
N20657719: C59.2 D18.1(I/O1) L19.1 R47.2
N20661131: J16.4 R49.2 R51.2
N21282940: R6.1 USB1.A5(CC1)
N21282980: R5.1 USB1.B5(CC2)
N21645459: J11.3(1) L12.1
N21647155: J11.4(2) L14.1
N21770345: J16.5 R45.2
N21935450: J16.2 L19.2
N21936924: J16.1 L18.2
N21955942: R37.2 SW1.1(NC)
N22004853: L20.1 R52.2 R55.2
N22004855: C61.2 J17.2(A) L20.2
N22004859: C60.2 J17.5(D) L21.2
N22004899: L21.1 R53.2 R54.2
N22136605: J16.3 R48.2 R50.2
N22406837: C55.2 L17.1 R56.2
N22406846: C54.2 L16.1 R57.2
N22416143: C10.2 C11.2 R12.1 R14.1 R15.2 R17.1 U1.8(VCC)
N22416253: R14.2 U1.7(HOLD#)
N22416257: R17.2 R19.1 U1.3(WP#)
N22434611: C14.1 L4.1
N22445149: C47.2 J12.2 L11.2
N22445174: C44.2 L13.1 R41.2
N22445178: C49.2 J12.1 L13.2
N22445483: C42.2 L11.1 R42.2
N22447922: J4.1 L2.2
N22447925: J4.3 L3.2
N22458001: C65.2 R58.2 R59.1 U3.5(+IN)
N22458253: C62.2 R67.2 U3.7(OUT)
N22458339: C63.2 R68.2 U3.1(OUT)
N22458342: C66.1 R64.2 R65.2 U3.3(+IN)
N22459042: R60.2 R67.1 U3.6(-IN)
N22459098: R66.2 R68.1 U3.2(-IN)
N22461340: J18.3(1) R60.1
N22461343: J18.4(2) R66.1
N22461425: C63.1 J19.2(4)
N22485892: D2.2(K) L1.1
N22494608: LED0.2(DOUT) LED1.4(DIN)
N22494794: LED1.2(DOUT) LED2.4(DIN)
N22495087: LED2.2(DOUT) LED3.4(DIN)
N22495197: LED3.2(DOUT) LED4.4(DIN)
N22495311: LED4.2(DOUT) LED5.4(DIN)
N22495415: C78.1 C79.1 LED6.3(VDD) LED7.3(VDD)
N22495427: LED5.2(DOUT) LED6.4(DIN)
N22495546: LED6.2(DOUT) LED7.4(DIN)
N22495670: LED7.2(DOUT) LED8.4(DIN)
N22495793: LED8.2(DOUT) LED9.4(DIN)
N22495925: LED9.2(DOUT) LED10.4(DIN)
N22496058: LED10.2(DOUT) LED11.4(DIN)
N22496193: LED11.2(DOUT) LED12.4(DIN)
N22496331: LED12.2(DOUT) LED13.4(DIN)
N22496473: LED13.2(DOUT) LED14.4(DIN)
N22503567: J15.5 R76.2
N22503848: J12.5 R75.2
N22530579: J4.5 L22.2
N22535031: C48.2 R39.1 R40.1
N22535043: C62.1 J19.1(3)

Not connected (* = marked no-connect by the designer): J10 3(B) 4(C); J14 3(B) 4(C); J17 3(B) 4(C); LED14 2(DOUT)*; USB1 A2(SSTXp1) A3(SSTXn1) A8(SBU1) A10(SSRXn2) A11(SSRXp2) B2(SSTXp2) B3(SSTXn2) B8(SBU2) B10(SSRXn1) B11(SSRXp1)

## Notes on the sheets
sheet 1
- 1.00
- Initial Version
- Brad Wu
- 2020/09/07
- 1.01
- Add Mic In OP, ARGB pin, VR Voltage level.
- Brad Wu
- 2020/11/16
- 1.02
- Modify Mic In C42,C43, C44, C50,C54,C55 value to 475.
- Brad Wu
- 2021/1/5
- 1.03
- 1.Add Test Pin R71 1kOhm.
- Brad Wu
- 2021/1/21
- 2.Modify HP out R46, R47,R52, R53.
- 1.04
- 1.Add C68, C69(106).
- Brad Wu
- 2021/2/5
- 2.Modify C41 to 475, HP out R46, R47,R52, R53 to 33R or 5R1.
- 1.05
- 1.Modify L11, L13 to capactor 475 value.
- Brad Wu
- 2021/5/25
- 2.Modify C42, C44, to 0R, R41, R42 to 1MOhm. for fine tune
   high frequency noise.
- 1.06
- 1.For suspend current modify R27, R28 value. And  add diode D2.
- Brad Wu
- 2021/7/27
- 1.07
- 1.§R°£C1/R1/VR1
  2.§R°£C6/R4/VR2
  3.§R°£C9/R8/VR3
  4.§R°£R35/J6/C12/D1/R11/R13/R16/R20/R21/R24/Q1/Q2/Q3
  5.Add D2
  C68/C69
  R72/R73/R74/C70/C71/SW6
  LED~LED14(¦@15Áû)
  C72~C86¦@14Áû
  ´«®ÆJ12/J15
- Brad Wu
- 2022/09/29
- 1.08
- For Pass ESD modify:
  1.0R L5/L6/L7/L8/L9/L10.
  2, TVS D15/D16/D17/D18/D19/D20.
  3. L23 Fead 100R.
  4. C7, C8 ESD pass change to TVS D21, D22.
- Brad Wu
- 2024/10/30
sheet 4
- USB Type C
- Test Mode
- Function Switch
  Beauty voice/Hi Res Mode
- GPIO_0    ARGB Control
  GPIO_1    Beauty voice/Hi-Res
  GPIO_2    AGC button
  GPIO_3    Voice prompt
  GPIO_4    ARGB LED button
  GPIO_5    MIC mute On/Off button
  GPIO_6    Encoder button
  GPIO_7    Headphone JD
  GPIO_8    Volume Encoder
  GPIO_9    Volume Encoder
  GPIO_10   UART
  GPIO_11   UART
  GPIO_16   Line In JD
  GPIO_17   Music In JD
  GPIO_18   Resver button
  GPIO_19   Resver button
- Beauty voice  mode
- Hi Res mode
- I2C
- GND_EARTH
- GND_EARTH
- GND_EARTH
- Close IC Pin
- UART
- FLASH
- QFN68 pin Socket
- Buttons
- Crystal
- Clipping
- Vocal Remover
- AGC button
- Voice prompt button
- ARGB LED button
- GND_EARTH
- DGND
- GND_EARTH
- AGND
- DGND
- AGND
- GND_Plane
- Reserve button
- Close IC Pin
- Reserve button
- MIC mute button
- Close IC Pin
- Close SW5
- Close IC Pin
sheet 5
- J11 Stereo MIC1+MIC2
- MIC2
- Music In
- ARGB Pin
- MIC1
- Line In
- MIC In +20 dB
- HP2
- ENCODER(VOLUME+/-)
- Bypass OP
- CTIA¡GL/R/GND/MIC
- HP1+Mic1
- TVS  Default NC(For ESD)
- LED Closed circular the Encoder
